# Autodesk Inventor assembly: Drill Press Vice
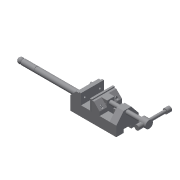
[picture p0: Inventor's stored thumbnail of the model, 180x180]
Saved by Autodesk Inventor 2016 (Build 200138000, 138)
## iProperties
Created: 2009-05
Part Number: Drill Press Vice
Document SubType Name: Assembly
Designer: Sham
Author: Sham
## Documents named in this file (9)
- D:\KAVITA\Autodesk Inventor_2015_By Avijeet\Inventor_psrtfiles_2015\Inventor_2015_tut\c12_Inv_tut_2015\c12_tut03_inv\Drill Press Vice.iam
- D:\KAVITA\Autodesk Inventor_2015_By Avijeet\Inventor_psrtfiles_2015\Inventor_2015_tut\c12_Inv_tut_2015\c12_tut03_inv\Base.ipt
- D:\KAVITA\Autodesk Inventor_2015_By Avijeet\Inventor_psrtfiles_2015\Inventor_2015_tut\c12_Inv_tut_2015\c12_tut03_inv\Safety Handle.ipt
- D:\KAVITA\Autodesk Inventor_2015_By Avijeet\Inventor_psrtfiles_2015\Inventor_2015_tut\c12_Inv_tut_2015\c12_tut03_inv\Jaw Face.ipt
- D:\KAVITA\Autodesk Inventor_2015_By Avijeet\Inventor_psrtfiles_2015\Inventor_2015_tut\c12_Inv_tut_2015\c12_tut03_inv\Movable Jaw.ipt
- D:\KAVITA\Autodesk Inventor_2015_By Avijeet\Inventor_psrtfiles_2015\Inventor_2015_tut\c12_Inv_tut_2015\c12_tut03_inv\Cap Screw.ipt
- D:\KAVITA\Autodesk Inventor_2015_By Avijeet\Inventor_psrtfiles_2015\Inventor_2015_tut\c12_Inv_tut_2015\c12_tut03_inv\Clamp Screw Handle.ipt
- D:\KAVITA\Autodesk Inventor_2015_By Avijeet\Inventor_psrtfiles_2015\Inventor_2015_tut\c12_Inv_tut_2015\c12_tut03_inv\Clamp Screw.ipt
- D:\KAVITA\Autodesk Inventor_2015_By Avijeet\Inventor_psrtfiles_2015\Inventor_2015_tut\c12_Inv_tut_2015\c12_tut03_inv\Handle Stop.ipt
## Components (13 placed, 8 different names)
1. Base:1 — Mate:2, Mate:3, Mate:7, Insert:10, Insert:11, Insert:12, Insert:13
2. Safety Handle:1
3. Jaw Face:1 — Insert:8, Insert:9, Mate:7
4. Jaw Face:2 — Insert:10, Insert:11
5. Movable Jaw:1 — Mate:2, Mate:3, Insert:2, Insert:3, Insert:4, Insert:8, Insert:9
6. Cap Screw:1 — Insert:2
7. Cap Screw:2 — Insert:3
8. Cap Screw:3 — Insert:13
9. Cap Screw:4 — Insert:12
10. Clamp Screw:1 — Insert:4, Mate:6, Rotation/Translation:2
11. Clamp Screw Handle:1 — Mate:6, Insert:5, Insert:6, Rotation/Translation:2
12. Handle Stop:1 — Insert:6, Mate:8
13. Handle Stop:2 — Insert:5
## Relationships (17: Insert 11, Mate 5, RelateRotateTranslate 1)
- Mate:2: Base:1 ↔ Movable Jaw:1
- Mate:3: Base:1 ↔ Movable Jaw:1
- Insert:2: Movable Jaw:1 ↔ Cap Screw:1
- Insert:3: Movable Jaw:1 ↔ Cap Screw:2
- Insert:4: Movable Jaw:1 ↔ Clamp Screw:1
- Mate:6: Clamp Screw:1 ↔ Clamp Screw Handle:1
- Insert:5: Clamp Screw Handle:1 ↔ Handle Stop:2
- Insert:6: Clamp Screw Handle:1 ↔ Handle Stop:1
- Insert:8: Jaw Face:1 ↔ Movable Jaw:1
- Insert:9: Jaw Face:1 ↔ Movable Jaw:1
- Mate:7: Base:1 ↔ Jaw Face:1
- Rotation/Translation:2 [RelateRotateTranslate]: Clamp Screw:1 ↔ Clamp Screw Handle:1
- Mate:8: Handle Stop:1
- Insert:10: Base:1 ↔ Jaw Face:2
- Insert:11: Base:1 ↔ Jaw Face:2
- Insert:12: Base:1 ↔ Cap Screw:4
- Insert:13: Base:1 ↔ Cap Screw:3
